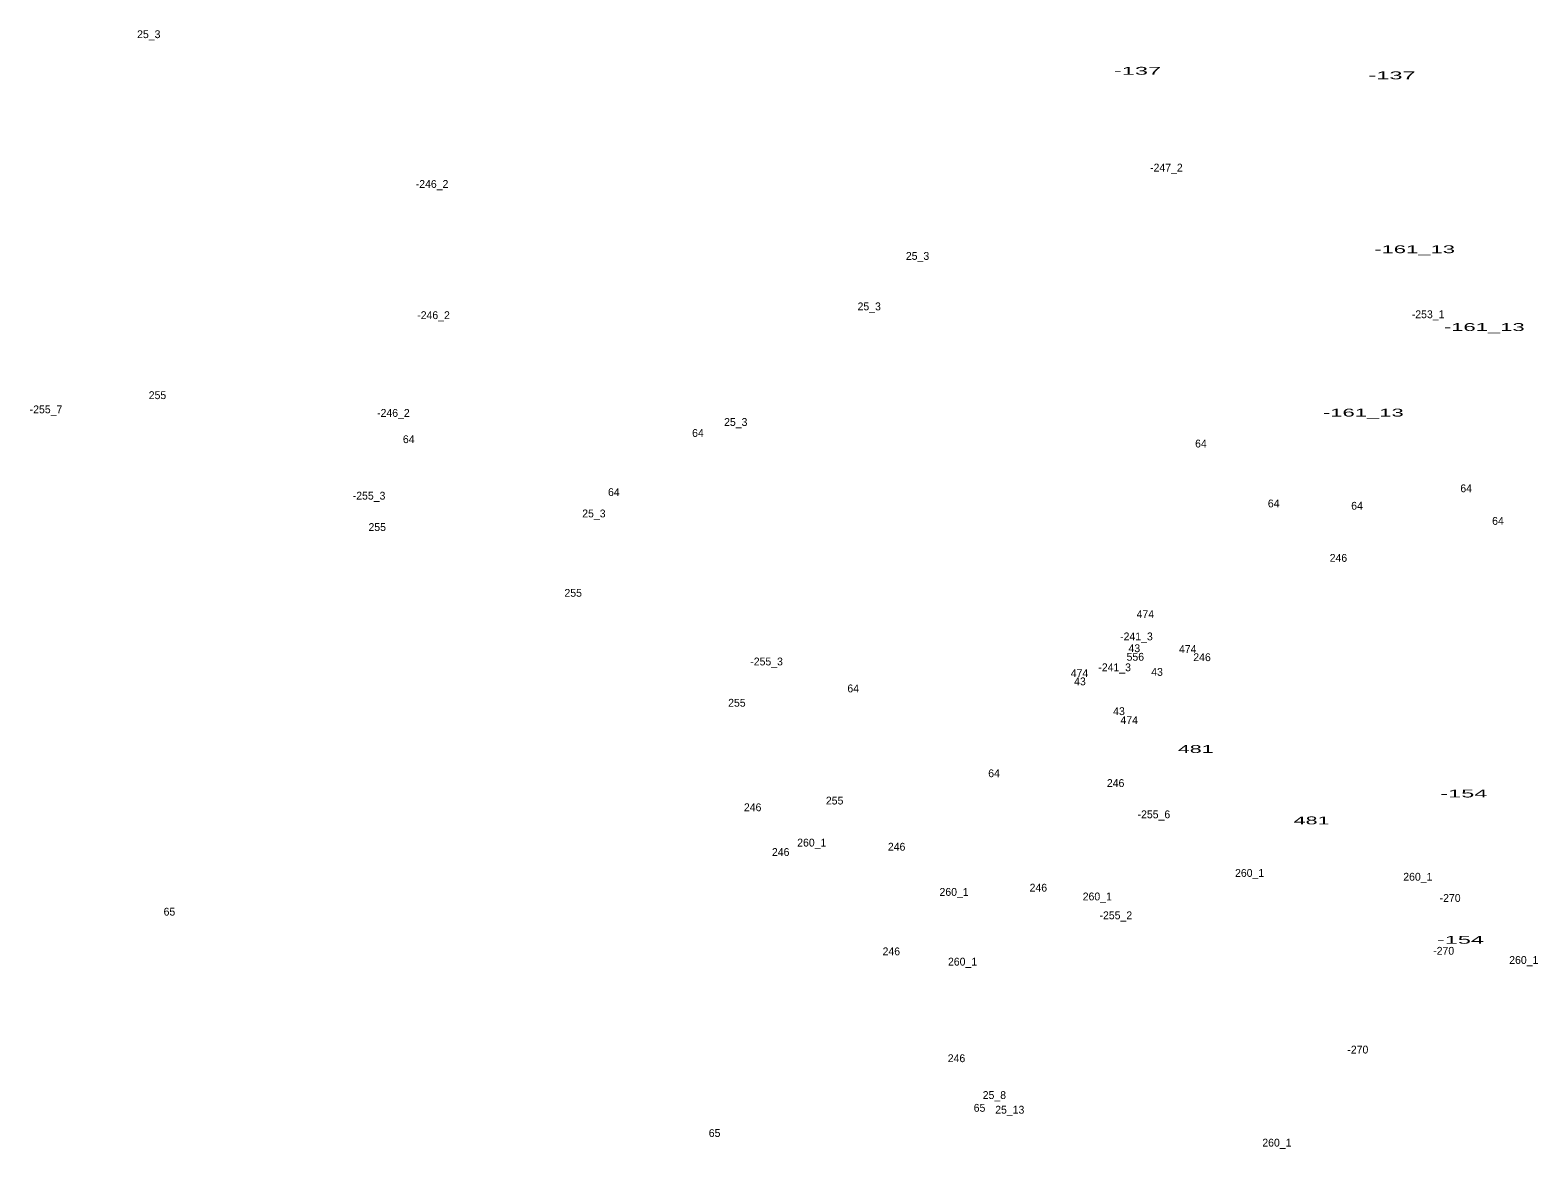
# Model space of a CAD drawing. Extents: x -661742 to -657295, y -1002932 to -996888.
# Drawn here: x -659253 to -658483, y -1000986 to -1000415 of the extents above; entities that cross this region are included whole.
import ezdxf
from ezdxf.enums import TextEntityAlignment as Align

# ---------------------------------------------------------------- set-up
doc = ezdxf.new("R2010")
doc.units = 0
doc.header["$LTSCALE"] = 1.6
doc.layers.add('24', color=7, linetype='Continuous')

msp = doc.modelspace()

# ---------------------------------------------------------------- texts
at = {"layer": '24'}
for s, p in [('25_3', (-659192.085, -1000419.02)), ('-247_2', (-658672.672, -1000487.14)), ('-246_2', (-659047.502, -1000495.49)), ('25_3', (-658799.695, -1000532.2)), ('-246_2', (-659046.732, -1000562.43)), ('25_3', (-658824.365, -1000557.95)), ('-253_1', (-658539.086, -1000561.98)), ('255', (-659187.657, -1000603.27)), ('-255_7', (-659244.548, -1000610.52)), ('-246_2', (-659067.232, -1000612.34)), ('25_3', (-658892.485, -1000616.97)), ('64', (-659059.407, -1000625.75)), ('64', (-658911.767, -1000622.57)), ('64', (-658655.047, -1000627.98)), ('-255_3', (-659079.652, -1000654.57)), ('64', (-658954.707, -1000652.75)), ('64', (-658519.667, -1000650.81)), ('25_3', (-658964.885, -1000663.65)), ('64', (-658617.917, -1000658.55)), ('64', (-658575.367, -1000659.71)), ('255', (-659075.487, -1000670.6)), ('64', (-658503.427, -1000667.45)), ('246', (-658584.867, -1000686.33)), ('255', (-658975.457, -1000704.17)), ('474', (-658683.401, -1000715.01)), ('-241_3', (-658687.97, -1000726.41)), ('43', (-658689.041, -1000732.43)), ('474', (-658661.791, -1000732.86)), ('-255_3', (-658876.742, -1000739.2)), ('-241_3', (-658699.09, -1000742.18)), ('556', (-658688.533, -1000736.81)), ('246', (-658654.487, -1000737.02)), ('474', (-658717.041, -1000745.17)), ('43', (-658716.791, -1000749.35)), ('43', (-658677.441, -1000744.51)), ('64', (-658832.517, -1000752.95)), ('255', (-658891.907, -1000760.28)), ('43', (-658696.871, -1000764.55)), ('474', (-658691.641, -1000769.12)), ('64', (-658760.647, -1000796.27)), ('246', (-658698.587, -1000801.25)), ('255', (-658842.017, -1000810.19)), ('246', (-658883.857, -1000813.63)), ('-255_6', (-658679.048, -1000817.22)), ('260_1', (-658853.688, -1000831.66)), ('246', (-658810.367, -1000833.75)), ('246', (-658869.547, -1000836.46)), ('260_1', (-658630.198, -1000847.14)), ('260_1', (-658544.328, -1000849.08)), ('260_1', (-658781.048, -1000856.82)), ('246', (-658738.037, -1000854.65)), ('260_1', (-658707.948, -1000859.14)), ('-270', (-658527.854, -1000859.92)), ('65', (-659181.553, -1000866.9)), ('-255_2', (-658698.482, -1000868.76)), ('246', (-658813.077, -1000887.15)), ('-270', (-658531.144, -1000886.88)), ('260_1', (-658776.718, -1000892.41)), ('260_1', (-658490.258, -1000891.56)), ('246', (-658779.817, -1000941.71)), ('-270', (-658574.964, -1000937.3)), ('25_8', (-658760.485, -1000960.51)), ('65', (-658768.063, -1000967.03)), ('25_13', (-658752.619, -1000967.99)), ('65', (-658903.283, -1000979.88)), ('260_1', (-658616.278, -1000984.8))]:
    msp.add_text(s, height=4, dxfattribs=at).set_placement(p, align=Align.CENTER)
for s, width, p in [('-137', 2.25, (-658687.415, -1000437.71)), ('-137', 2.25, (-658557.525, -1000440.03)), ('-161_13', 2.1, (-658545.989, -1000528.79)), ('-161_13', 2.1, (-658510.419, -1000568.5)), ('-161_13', 2.1, (-658572.159, -1000612.18)), ('481', 2.05, (-658657.703, -1000783.87)), ('-154', 2.25, (-658520.846, -1000806.59)), ('481', 2.05, (-658598.573, -1000820.33)), ('-154', 2.25, (-658522.586, -1000881.26))]:
    msp.add_text(s, height=4, dxfattribs=dict(at, width=width)).set_placement(p, align=Align.CENTER)

doc.saveas('drawing.dxf')
